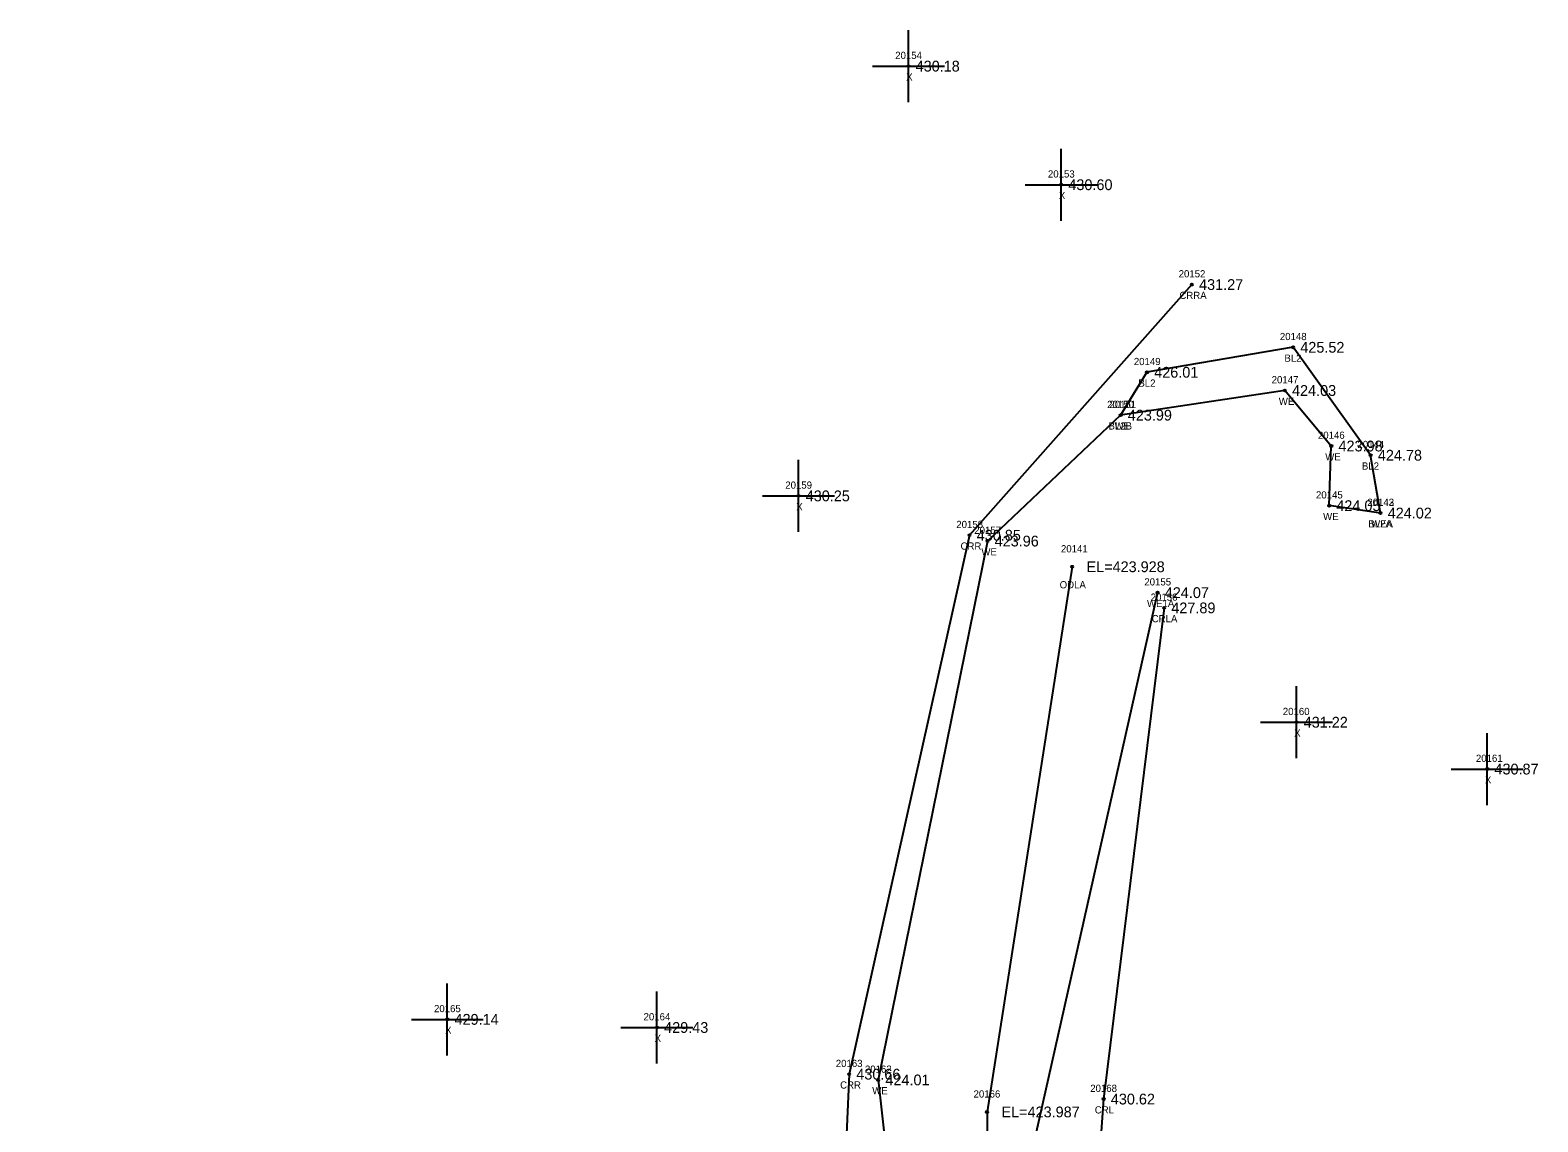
# Model space of a CAD drawing. Extents: x 1858461 to 1858936, y 1147060 to 1148183.
# Drawn here: x 1858722.2 to 1858931.8, y 1148031.1 to 1148182.8 of the extents above; entities that cross this region are included whole.
import ezdxf

# ---------------------------------------------------------------- set-up
doc = ezdxf.new("R2010")
doc.units = 0
for name, color, linetype in [('RD_DTM_BkLn1', 7, 'Continuous'), ('RD_DTM_BkLn_txCode', 7, 'Continuous'), ('RD_EX_H2O', 7, 'Continuous'), ('RD_EX_H2O_txCode', 7, 'Continuous'), ('RD_EX_Misc', 7, 'Continuous'), ('RD_EX_Misc_txCode', 7, 'Continuous'), ('RD_EX_TX_H2O_ELEV', 7, 'Continuous'), ('RD_EX_TX_Misc_ELEV', 7, 'Continuous'), ('RD_SMD_Locator', 7, 'Continuous')]:
    doc.layers.add(name, color=color, linetype=linetype)

msp = doc.modelspace()

# ---------------------------------------------------------------- linework, layer by layer
at = {"layer": 'RD_DTM_BkLn1'}
msp.add_lwpolyline([(1858909.91, 1148115.72), (1858908.54, 1148123.76), (1858897.76, 1148138.76), (1858877.45, 1148135.29), (1858873.78, 1148129.33)], dxfattribs=at)
at = {"layer": 'RD_EX_H2O'}
for points in [[(1858883.69, 1148147.48), (1858852.78, 1148112.64), (1858836.04, 1148037.73), (1858833.26, 1147975.2), (1858828.33, 1147910.84), (1858842, 1147848.22), (1858847.52, 1147794.04), (1858841.16, 1147786.48), (1858816.23, 1147769.28), (1858759.58, 1147742.8), (1858751.47, 1147732.35), (1858731.2, 1147689.66), (1858724.77, 1147677.64), (1858718.76, 1147662.14), (1858713.87, 1147646.5), (1858696.23, 1147629.99), (1858681.73, 1147631.9), (1858663.61, 1147613.98)], [(1858909.91, 1148115.72), (1858902.77, 1148116.75), (1858903.07, 1148125.04), (1858896.61, 1148132.76), (1858873.78, 1148129.33), (1858855.27, 1148111.83), (1858840.09, 1148036.93), (1858846.14, 1147982.36), (1858846.9, 1147967.54), (1858840.1, 1147928.32), (1858835.96, 1147922.3), (1858846.22, 1147851.69), (1858849.56, 1147834.44), (1858863.29, 1147789.22), (1858867.71, 1147772.35), (1858865.71, 1147761.59), (1858842.61, 1147761.06), (1858828.27, 1147754.21), (1858821.34, 1147763.04), (1858764.94, 1147737.1), (1858734.3, 1147688.97), (1858719.03, 1147640.86), (1858697.04, 1147613.49)], [(1858867.04, 1148108.26), (1858855.22, 1148032.48), (1858854.94, 1147976.71), (1858844.75, 1147924.02), (1858838.88, 1147914.94), (1858851.14, 1147854.11), (1858872.36, 1147792.48), (1858884.3, 1147779.68), (1858885.3, 1147773.97), (1858872.32, 1147746.91), (1858824.97, 1147749.39), (1858805.62, 1147746.07), (1858768.36, 1147727.81), (1858744.99, 1147687.5), (1858739.82, 1147673.18), (1858724.58, 1147638.24), (1858698.73, 1147607.87)], [(1858878.92, 1148104.66), (1858861.55, 1148027.41), (1858861.16, 1147976.95), (1858850.44, 1147924.2), (1858843.19, 1147917.77), (1858850.23, 1147884.47), (1858857.83, 1147857.85), (1858871.27, 1147824.7), (1858889.75, 1147780), (1858881.97, 1147738.22), (1858867.37, 1147736.75), (1858826.32, 1147742.88), (1858795.91, 1147734.53), (1858775.64, 1147718.51), (1858753.77, 1147690.47), (1858731.96, 1147634.67), (1858700.72, 1147599.99)], [(1858879.83, 1148102.54), (1858871.42, 1148034.27), (1858866.93, 1147971.73), (1858863.21, 1147909.44), (1858860.9, 1147860.04), (1858873.82, 1147825.54), (1858891.79, 1147781.55), (1858894.95, 1147773.07), (1858887.01, 1147735.25), (1858825.08, 1147733.03), (1858791.14, 1147702.41), (1858765.02, 1147654.77), (1858740.99, 1147628.76), (1858706.35, 1147596.83), (1858671.87, 1147580.02), (1858637.61, 1147560.56), (1858613.46, 1147539.88), (1858609.2, 1147499), (1858608.26, 1147474.71), (1858583.43, 1147442.99), (1858542.68, 1147417.32), (1858497.34, 1147430.55)]]:
    msp.add_lwpolyline(points, dxfattribs=at)
at = {"layer": 'RD_EX_Misc'}
for p, q in [((1858844.29, 1148172.84), (1858844.29, 1148182.84)), ((1858839.29, 1148177.84), (1858849.29, 1148177.84)), ((1858865.52, 1148156.36), (1858865.52, 1148166.36)), ((1858860.52, 1148161.36), (1858870.52, 1148161.36)), ((1858829.01, 1148113.11), (1858829.01, 1148123.11)), ((1858824.01, 1148118.11), (1858834.01, 1148118.11)), ((1858898.23, 1148081.65), (1858898.23, 1148091.65)), ((1858893.23, 1148086.65), (1858903.23, 1148086.65)), ((1858924.75, 1148075.14), (1858924.75, 1148085.14)), ((1858919.75, 1148080.14), (1858929.75, 1148080.14)), ((1858780.19, 1148040.35), (1858780.19, 1148050.35)), ((1858809.33, 1148039.22), (1858809.33, 1148049.22)), ((1858775.19, 1148045.35), (1858785.19, 1148045.35)), ((1858804.33, 1148044.22), (1858814.33, 1148044.22))]:
    msp.add_line(p, q, dxfattribs=at)
at = {"layer": 'RD_SMD_Locator'}
for centre in [(1858844.29, 1148177.84), (1858865.52, 1148161.36), (1858883.69, 1148147.48), (1858897.76, 1148138.76), (1858877.45, 1148135.29), (1858896.61, 1148132.76), (1858873.78, 1148129.33), (1858873.78, 1148129.33), (1858903.07, 1148125.04), (1858908.54, 1148123.76), (1858829.01, 1148118.11), (1858902.77, 1148116.75), (1858909.91, 1148115.72), (1858909.91, 1148115.72), (1858852.78, 1148112.64), (1858855.27, 1148111.83), (1858867.04, 1148108.26), (1858878.92, 1148104.66), (1858879.83, 1148102.54), (1858898.23, 1148086.65), (1858924.75, 1148080.14), (1858780.19, 1148045.35), (1858809.33, 1148044.22), (1858836.04, 1148037.73), (1858840.09, 1148036.93), (1858871.42, 1148034.27), (1858855.22, 1148032.48)]:
    msp.add_circle(centre, 0.15, dxfattribs=at)

# ---------------------------------------------------------------- texts
at = {"layer": 'RD_DTM_BkLn_txCode'}
for s, p in [('20148', (1858895.92, 1148139.76)), ('20149', (1858875.62, 1148136.29)), ('BL2', (1858896.55, 1148136.76)), ('BL2', (1858876.25, 1148133.29)), ('20150', (1858871.91, 1148130.33)), ('BL2B', (1858872.1, 1148127.33)), ('20144', (1858906.7, 1148124.76)), ('BL2', (1858907.33, 1148121.76)), ('20143', (1858908.08, 1148116.72)), ('BL2A', (1858908.22, 1148113.72))]:
    msp.add_text(s, height=1, dxfattribs=at).set_placement(p)
at = {"layer": 'RD_EX_H2O_txCode'}
for s, p in [('20152', (1858881.85, 1148148.48)), ('CRRA', (1858881.95, 1148145.48)), ('20147', (1858894.78, 1148133.76)), ('20151', (1858872.23, 1148130.33)), ('WE', (1858895.77, 1148130.76)), ('WE', (1858872.94, 1148127.33)), ('20146', (1858901.21, 1148126.04)), ('WE', (1858902.23, 1148123.04)), ('20145', (1858900.94, 1148117.75)), ('20142', (1858908.08, 1148116.72)), ('WE', (1858901.93, 1148114.75)), ('20158', (1858850.94, 1148113.64)), ('20157', (1858853.44, 1148112.83)), ('WEA', (1858908.6, 1148113.72)), ('CRR', (1858851.53, 1148110.64)), ('20141', (1858865.49, 1148110.26)), ('WE', (1858854.43, 1148109.83)), ('ODLA', (1858865.31, 1148105.26)), ('20155', (1858877.08, 1148105.66)), ('WE1A', (1858877.45, 1148102.66)), ('20156', (1858877.97, 1148103.54)), ('CRLA', (1858878.11, 1148100.54)), ('20163', (1858834.19, 1148038.73)), ('20162', (1858838.24, 1148037.93)), ('CRR', (1858834.79, 1148035.73)), ('WE', (1858839.26, 1148034.93)), ('20168', (1858869.56, 1148035.27)), ('20166', (1858853.34, 1148034.48)), ('CRL', (1858870.19, 1148032.27))]:
    msp.add_text(s, height=1, dxfattribs=at).set_placement(p)
at = {"layer": 'RD_EX_Misc_txCode'}
for s, p in [('20154', (1858842.45, 1148178.84)), ('X', (1858843.97, 1148175.84)), ('20153', (1858863.68, 1148162.36)), ('X', (1858865.2, 1148159.36)), ('20159', (1858827.17, 1148119.11)), ('X', (1858828.69, 1148116.11)), ('20160', (1858896.33, 1148087.65)), ('X', (1858897.91, 1148084.65)), ('20161', (1858923.17, 1148081.14)), ('X', (1858924.43, 1148078.14)), ('20165', (1858778.34, 1148046.35)), ('20164', (1858807.47, 1148045.22)), ('X', (1858779.88, 1148043.35)), ('X', (1858809.01, 1148042.22))]:
    msp.add_text(s, height=1, dxfattribs=at).set_placement(p)
at = {"layer": 'RD_EX_TX_H2O_ELEV'}
for s, p in [('431.27', (1858884.69, 1148146.73)), ('424.03', (1858897.61, 1148132.01)), ('423.99', (1858874.78, 1148128.58)), ('423.98', (1858904.07, 1148124.29)), ('424.05', (1858903.77, 1148116)), ('424.02', (1858910.91, 1148114.97)), ('430.85', (1858853.78, 1148111.89)), ('423.96', (1858856.27, 1148111.08)), ('EL=423.928', (1858869.04, 1148107.51)), ('424.07', (1858879.92, 1148103.91)), ('427.89', (1858880.83, 1148101.79)), ('430.66', (1858837.04, 1148036.98)), ('424.01', (1858841.09, 1148036.18)), ('430.62', (1858872.42, 1148033.52)), ('EL=423.987', (1858857.22, 1148031.73))]:
    msp.add_text(s, height=1.5, dxfattribs=at).set_placement(p)
at = {"layer": 'RD_EX_TX_Misc_ELEV'}
for s, p in [('430.18', (1858845.29, 1148177.09)), ('430.60', (1858866.52, 1148160.61)), ('425.52', (1858898.76, 1148138.01)), ('426.01', (1858878.45, 1148134.54)), ('423.99', (1858874.78, 1148128.58)), ('424.78', (1858909.54, 1148123.01)), ('430.25', (1858830.01, 1148117.36)), ('424.02', (1858910.91, 1148114.97)), ('431.22', (1858899.23, 1148085.9)), ('430.87', (1858925.75, 1148079.39)), ('429.14', (1858781.19, 1148044.6)), ('429.43', (1858810.33, 1148043.47))]:
    msp.add_text(s, height=1.5, dxfattribs=at).set_placement(p)

doc.saveas('drawing.dxf')
